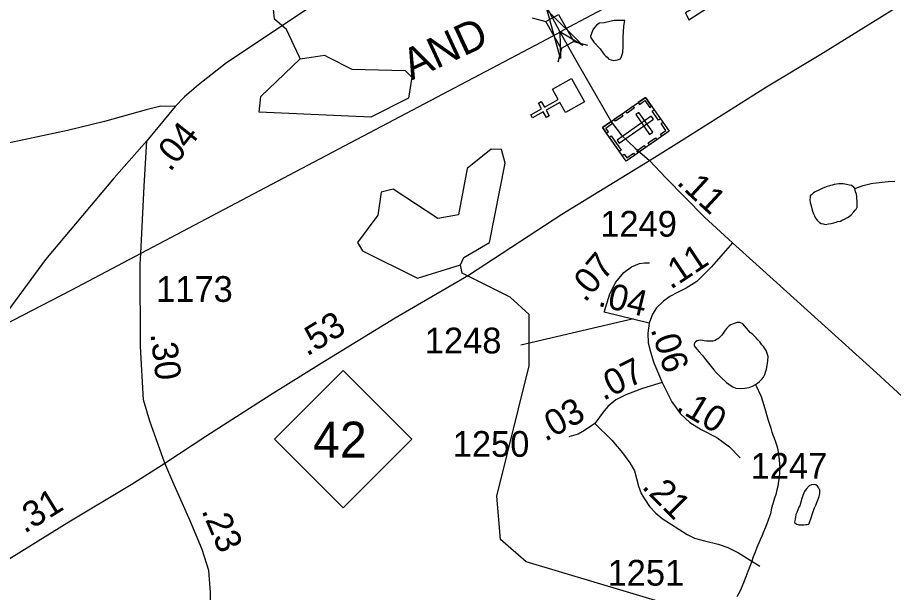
# Model space of a CAD drawing. Extents: x 2001466 to 2224147, y 644118 to 847247.
# Drawn here: x 2043849 to 2048097, y 660715 to 663505 of the extents above; entities that cross this region are included whole.
import ezdxf

# ---------------------------------------------------------------- set-up
doc = ezdxf.new("R2010")
doc.units = 0
for name, color, linetype in [('Exist Cultural Cemetery CELL', 7, 'Continuous'), ('Exist Cultural Church CELL', 7, 'Continuous'), ('Exist Hydrographic Creek Single Shore', 7, 'Continuous'), ('Exist Hydrographic Misc Water Feature', 7, 'Continuous'), ('Exist Railroad Mainline', 7, 'Continuous'), ('Exist Railroad Mainline Label', 7, 'Continuous'), ('Exist Road Primary NC Attributed', 7, 'Continuous'), ('Exist Road Primary NC Service Mileage Hundredths English Label', 7, 'Continuous'), ('Exist Road Primary NC Shield CELL', 7, 'Continuous'), ('Exist Road Primary NC Shield Number Label', 7, 'Continuous'), ('Exist Road Secondary Mileage Hundredths English Label', 7, 'Continuous'), ('Exist Road Secondary Structure Standard Bridge Attributed CELL', 7, 'Continuous'), ('Exist Road Secondary Structure Standard Bridge CELL', 7, 'Continuous'), ('Exist Road Secondary Type 51 Attributed', 7, 'Continuous'), ('Exist Road Secondary Type 51 Number Label', 7, 'Continuous')]:
    doc.layers.add(name, color=color, linetype=linetype)

msp = doc.modelspace()

# ---------------------------------------------------------------- linework, layer by layer
at = {"layer": 'Exist Cultural Cemetery CELL'}
for points in [[(2046894.6, 663117.1), (2047009, 662954.1), (2046800.6, 662807.9), (2046686.2, 662970.8)], [(2046859.2, 663092.2), (2046865.7, 663082.9), (2046892, 663101.4), (2046915.3, 663068.2), (2046924.4, 663074.6), (2046894.6, 663117.1)], [(2046798.4, 663049.6), (2046833.9, 663074.5), (2046840.4, 663065.2), (2046805, 663040.3)], [(2046743.4, 663011), (2046778.9, 663035.9), (2046785.4, 663026.6), (2046750, 663001.7)], [(2046933.3, 663011), (2046922.5, 663026.3), (2046756.5, 662909.8), (2046767.3, 662894.5)], [(2046862.3, 663044.6), (2046847.1, 663033.9), (2046914.7, 662937.5), (2046930, 662948.2)], [(2046937.1, 663056.5), (2046966.9, 663014), (2046957.6, 663007.5), (2046927.8, 663049.9)], [(2046705.2, 662943.8), (2046714.6, 662950.4), (2046702, 662968.4), (2046735.1, 662991.6), (2046728.7, 663000.7), (2046686.2, 662970.9)], [(2046973.5, 662929.2), (2046967, 662938.5), (2046993.4, 662957), (2046970, 662990.2), (2046979.2, 662996.5), (2047009, 662954.1)], [(2046728.6, 662930.4), (2046777.3, 662860.9), (2046768, 662854.4), (2046719.3, 662923.8)], [(2046907.2, 662896.5), (2046942.6, 662921.4), (2046949.2, 662912.1), (2046913.7, 662887.2)], [(2046853.2, 662858.7), (2046888.6, 662883.6), (2046895.2, 662874.2), (2046859.7, 662849.4)], [(2046781.5, 662835), (2046790.9, 662841.6), (2046803.6, 662823.6), (2046836.6, 662846.8), (2046843, 662837.7), (2046800.6, 662807.9)]]:
    msp.add_lwpolyline(points, close=True, dxfattribs=at)
at = {"layer": 'Exist Cultural Church CELL'}
msp.add_lwpolyline([(2046506.8, 663043.4), (2046478.8, 663093), (2046412.4, 663055.7), (2046428.1, 663027.8), (2046414.2, 663020), (2046398.5, 663047.9), (2046346.1, 663018.4), (2046338.2, 663032.4), (2046390.7, 663061.8), (2046375, 663089.7), (2046388.9, 663097.6), (2046404.6, 663069.7), (2046471, 663106.9), (2046442.9, 663157.3), (2046535.7, 663209.4), (2046599.6, 663095.5)], close=True, dxfattribs=at)
at = {"layer": 'Exist Hydrographic Creek Single Shore'}
msp.add_lwpolyline([(2047208.2, 660449.1), (2047192.2, 660541.3), (2046975.3, 660667.1), (2046316.2, 660864.2), (2046191.2, 660971.7), (2046174.1, 661182.1), (2046331.2, 661815.3), (2046331.2, 662064.7), (2046239.1, 662148.6), (2046005.2, 662264.9), (2045997.2, 662304.5)], dxfattribs=at)
at = {"layer": 'Exist Hydrographic Misc Water Feature'}
for q in [(2045216.5, 663312.6), (2045274.7, 663312.6)]:
    msp.add_line((2045220.2, 663304.5), q, dxfattribs=at)
for points in [[(2045216.5, 663312.6), (2045153.2, 663446.9), (2045095.4, 663497.3), (2045086.3, 663596), (2044903.2, 663780.1), (2044503.4, 663719.3)], [(2047088.3, 663527.6), (2047104.5, 663493.6), (2047218.1, 663565.8), (2047198.2, 663593.8), (2047088.3, 663527.6)], [(2046684.7, 663338.9), (2046694.8, 663324.9), (2046702.8, 663316.9), (2046708.7, 663312.8), (2046716.7, 663302.9), (2046728.8, 663298.9), (2046738.9, 663296.9), (2046758.7, 663299), (2046772.7, 663305), (2046778.8, 663315), (2046784.6, 663335), (2046786.6, 663365.1), (2046786.4, 663409), (2046790.3, 663463), (2046794.4, 663491), (2046742.3, 663490.9), (2046694.4, 663478.8), (2046672.4, 663476.8), (2046658.5, 663468.7), (2046646.6, 663456.7), (2046638.6, 663444.7), (2046630.6, 663422.7), (2046628.5, 663414.7), (2046628.7, 663408.7), (2046630.6, 663404.7), (2046644.7, 663384.8), (2046674.7, 663352.8), (2046684.7, 663338.9)], [(2045274.7, 663312.6), (2045337.3, 663321.8), (2045355.3, 663312.6)], [(2045355.3, 663312.6), (2045470.2, 663253.5), (2045729.2, 663248.2), (2045762.2, 663214.8), (2045745.2, 663113.4), (2045562.3, 663022), (2045021.3, 663046.1), (2045029.3, 663121.4), (2045220.2, 663304.5)], [(2045997.2, 662304.5), (2046013.2, 662340.2), (2046138.3, 662413.2), (2046213.3, 662798.8), (2046196.3, 662864.7), (2046146.3, 662865.7), (2046029.2, 662773), (2045988.2, 662547.4), (2045888.3, 662529.8), (2045671.4, 662671.9), (2045613.3, 662656.8), (2045596.3, 662545.5), (2045497.3, 662413), (2045522.3, 662373.1), (2045789.3, 662239.8), (2045997.2, 662304.5)], [(2047909.7, 662675.3), (2047905.6, 662681.3), (2047899.7, 662685.2), (2047893.7, 662689.2), (2047883.7, 662691.2), (2047869.7, 662695.2), (2047853.5, 662697.1), (2047841.6, 662697.1), (2047831.6, 662697.1), (2047809.6, 662695.1), (2047799.6, 662691.1), (2047791.6, 662689), (2047771.7, 662683), (2047751.8, 662675), (2047735.8, 662667), (2047717.8, 662658.9), (2047709.8, 662654.9), (2047699.7, 662644.9), (2047693.8, 662638.9), (2047693.8, 662632.9), (2047691.9, 662620.9), (2047693.8, 662606.9), (2047697.9, 662590.9), (2047703.8, 662570.9), (2047710, 662552.9), (2047714.1, 662542.9), (2047720, 662531), (2047728, 662520.9), (2047738.1, 662510.9), (2047746.1, 662504.9), (2047755.9, 662503), (2047768, 662501), (2047782, 662503.1), (2047795.9, 662505.1), (2047808, 662509.1), (2047819.9, 662511.1), (2047826, 662515.1), (2047840, 662517.1), (2047848, 662521.1), (2047860.1, 662527.2), (2047874, 662535.2), (2047882, 662539.2), (2047891.9, 662547.3), (2047905.8, 662561.3), (2047912, 662569.3), (2047915.9, 662575.3), (2047920, 662581.3), (2047921.8, 662585.3), (2047921.8, 662593.3), (2047921.8, 662601.3), (2047921.8, 662615.2), (2047919.7, 662627.2), (2047919.7, 662637.2), (2047917.7, 662647.3), (2047913.8, 662659.3), (2047911.8, 662667.3), (2047909.7, 662675.3)], [(2047909.7, 662675.3), (2047949.7, 662689.3), (2047989.7, 662699.4), (2048013.7, 662703.5), (2048071.7, 662709.6), (2048103.7, 662711.6)], [(2047427.4, 661724.5), (2047437.5, 661730.5), (2047447.5, 661738.5), (2047459.4, 661750.5), (2047467.4, 661760.6), (2047473.6, 661772.6), (2047477.2, 661784.6), (2047481.3, 661798.6), (2047485.2, 661816.6), (2047487.3, 661838.6), (2047489.1, 661860.6), (2047479.3, 661888.5), (2047473.1, 661898.6), (2047467.2, 661908.6), (2047459, 661916.6), (2047449.2, 661930.5), (2047439.1, 661940.5), (2047431.1, 661950.5), (2047415.1, 661966.5), (2047403, 661976.5), (2047385, 661998.4), (2047366.9, 662018.4), (2047353, 662024.3), (2047339, 662024.3), (2047324.9, 662020.2), (2047308.9, 662014.2), (2047300.9, 662008.2), (2047289, 661998.2), (2047281, 661988.2), (2047275.1, 661978.2), (2047265, 661964.2), (2047257, 661956.2), (2047249, 661948.1), (2047239.2, 661942.1), (2047233, 661938.1), (2047221.1, 661934.1), (2047211.3, 661934.1), (2047201.2, 661934.1), (2047191.2, 661934.1), (2047179.3, 661936), (2047173.2, 661938), (2047163.3, 661940), (2047153.3, 661938), (2047145.3, 661935.9), (2047137.3, 661931.9), (2047133.2, 661927.9), (2047131.3, 661919.9), (2047131.3, 661911.9), (2047137.3, 661903.9), (2047143.2, 661895.9), (2047155.3, 661882), (2047169.3, 661866), (2047187.3, 661844), (2047225.4, 661796.1), (2047239.4, 661780.2), (2047261.5, 661758.2), (2047287.4, 661734.2), (2047309.5, 661718.3), (2047317.5, 661712.3), (2047333.5, 661706.4), (2047355.6, 661704.4), (2047375.5, 661706.5), (2047397.7, 661710.5), (2047413.5, 661716.5), (2047427.4, 661724.5)], [(2047427.4, 661724.5), (2047455.5, 661666.6), (2047473.8, 661608.6), (2047487.9, 661556.7), (2047501.9, 661512.7), (2047508, 661492.7)], [(2047508, 661492.7), (2047524, 661450.8), (2047532, 661426.8), (2047536.1, 661408.8), (2047538.1, 661396.8), (2047540, 661380.8), (2047542.2, 661360.8), (2047544.3, 661336.8), (2047546.1, 661316.8), (2047544.3, 661300.8), (2047542.2, 661270.8), (2047540.4, 661254.8), (2047536.3, 661230.8), (2047532.4, 661212.8), (2047526.5, 661190.8), (2047520.5, 661172.8), (2047512.5, 661144.8), (2047506.6, 661124.8), (2047500.6, 661096.7), (2047490.8, 661070.7), (2047482.8, 661048.8), (2047476.8, 661032.8), (2047466.8, 661008.8), (2047458.8, 660988.7), (2047450.8, 660970.7), (2047435, 660932.7), (2047427, 660910.7), (2047417.2, 660888.6), (2047409, 660862.6), (2047401, 660840.6), (2047391.1, 660816.6), (2047381.3, 660790.6), (2047373.3, 660770.5), (2047359.3, 660734.6), (2047353.4, 660722.6), (2047337.4, 660694.6)], [(2047642.5, 661135), (2047638.6, 661129), (2047628.6, 661103), (2047624.5, 661093), (2047622.6, 661081), (2047620.8, 661073), (2047618.7, 661063), (2047616.7, 661057), (2047618.7, 661053), (2047628.8, 661047), (2047638.6, 661043.1), (2047662.6, 661043.1), (2047672.7, 661045.1), (2047678.6, 661045.1), (2047686.6, 661047.1), (2047690.7, 661055.2), (2047698.7, 661077.2), (2047706.5, 661103.1), (2047714.5, 661125.2), (2047720.6, 661139.2), (2047736.4, 661181.2), (2047740.5, 661195.2), (2047740.3, 661211.2), (2047734.4, 661225.2), (2047728.2, 661231.2), (2047720.2, 661237.1), (2047712.2, 661239.1), (2047700.3, 661237.1), (2047688.2, 661233.1), (2047674.5, 661217), (2047666.5, 661205.1), (2047658.5, 661185.1), (2047652.4, 661171.1), (2047642.5, 661135)]]:
    msp.add_lwpolyline(points, dxfattribs=at)
at = {"layer": 'Exist Railroad Mainline'}
for points in [[(2046464.5, 663426.2), (2046524.6, 663459.1), (2048551.7, 664535.4), (2049194.6, 664876.7), (2049524.4, 665051.8), (2049557.2, 665070.3), (2052622.8, 666680.7), (2055671.2, 668278.9), (2056997.6, 668963.3), (2058840.6, 669936.5)], [(2044448.5, 662360.9), (2045168.8, 662742.2), (2046388.6, 663384.6), (2046464.5, 663426.2)], [(2043613.8, 661924.4), (2043685.3, 661963.1), (2044109.1, 662181.3), (2044448.5, 662360.9)]]:
    msp.add_lwpolyline(points, dxfattribs=at)
at = {"layer": 'Exist Road Primary NC Attributed'}
for points in [[(2046913.8, 662811.7), (2047082.4, 662915.4), (2047481.7, 663167.8), (2047744.4, 663327), (2048387.5, 663726), (2048678.4, 663914.5), (2049061.4, 664156.9), (2049317.6, 664315.1), (2049692.4, 664549.5), (2049926.7, 664696), (2050073.1, 664788.3), (2050246.6, 664892.3), (2050426, 664989)], [(2044562.7, 661341.9), (2044762.5, 661472.9), (2045077, 661676), (2045321.9, 661827.9), (2045680.4, 662047.8), (2046035.7, 662254.1), (2046488.8, 662550.5), (2046747.8, 662708.6), (2046913.8, 662811.7)], [(2043161.8, 660484.8), (2043403.6, 660637.1), (2043704.5, 660815.2), (2044097.5, 661058.1), (2044399.9, 661239.3), (2044562.7, 661341.9)]]:
    msp.add_lwpolyline(points, dxfattribs=at)
at = {"layer": 'Exist Road Primary NC Shield CELL'}
msp.add_lwpolyline([(2045095.3, 661458.7), (2045428.3, 661791.7), (2045761.3, 661458.7), (2045428.3, 661125.7)], close=True, dxfattribs=at)
at = {"layer": 'Exist Road Secondary Structure Standard Bridge Attributed CELL'}
msp.add_lwpolyline([(2046482.2, 663305.8), (2046417.6, 663540.9), (2046591.1, 663369.5), (2046479.2, 663435.7)], close=True, dxfattribs=at)
at = {"layer": 'Exist Road Secondary Structure Standard Bridge CELL'}
for p, q in [((2046344.9, 663503.2), (2046411.4, 663485)), ((2046547.3, 663388.5), (2046613.8, 663370.3)), ((2046487.3, 663354.3), (2046469.1, 663287.8))]:
    msp.add_line(p, q, dxfattribs=at)
msp.add_lwpolyline([(2046472.7, 663519.9), (2046547.6, 663388.7), (2046486.2, 663353.7), (2046411.4, 663485)], close=True, dxfattribs=at)
at = {"layer": 'Exist Road Secondary Type 51 Attributed'}
msp.add_line((2046913, 662022.5), (2046694, 662074.9), dxfattribs=at)
for points in [[(2046205.8, 664180.3), (2046050.1, 664073.4), (2045655.3, 663822), (2045273.2, 663557.9), (2044862.6, 663285.4), (2044725.9, 663177.6), (2044659.4, 663119.5), (2044612.9, 663073)], [(2046233.7, 664047.4), (2046260.1, 663943.2), (2046346.6, 663692.4), (2046414, 663557.4), (2046479.2, 663435.7)], [(2044612.9, 663073), (2044543.8, 663074.1), (2044473.1, 663056.1), (2044271.5, 663000.2), (2044091, 662956.9), (2043589.5, 662850.2), (2043247.5, 662793.1), (2042932.4, 662735), (2042667.5, 662725.5), (2042397.2, 662731.9), (2042042.6, 662767.8), (2041866.8, 662796.3), (2041767.6, 662825.9), (2041627.2, 662858.6), (2041491.5, 662875.5), (2041144.3, 662882.9), (2040923.6, 662890.3), (2040808.6, 662928.3), (2040588.5, 663066.7), (2040278.1, 663276.9), (2040028.5, 663461.8), (2039952.5, 663496.6), (2039878.6, 663524.1)], [(2046479.2, 663435.7), (2046563.5, 663286.8), (2046730.6, 662996.5), (2046776.1, 662934.9), (2046845, 662870.4), (2046913.8, 662811.7)], [(2044612.9, 663073), (2044476.2, 662907.2)], [(2044476.2, 662907.2), (2044316.9, 662726.6), (2043984.3, 662331.5), (2043728.7, 661985.4)], [(2044446.6, 662360), (2044463.1, 662686.4), (2044476.2, 662907.2)], [(2046913.8, 662811.7), (2046993, 662726.6), (2047181.5, 662535.5), (2047317.1, 662412)], [(2047317.1, 662412), (2047214.3, 662295.6), (2047143.2, 662224.5), (2047092.7, 662190.9), (2047049.6, 662170.3), (2047012.2, 662151.6), (2046982.2, 662129.1), (2046948.5, 662095.5), (2046928, 662065.6), (2046913, 662022.5)], [(2047317.1, 662412), (2047529.3, 662218.6), (2048014.4, 661781.3), (2048220.7, 661592.2), (2048349.5, 661460.1), (2048474, 661313.3), (2048683.6, 661045), (2048847.2, 660838), (2049259.4, 660337.3), (2049468.9, 660074.3), (2049591.3, 659904.2), (2049771.3, 659592.6), (2049867.4, 659461.6), (2049949.2, 659385.6), (2050028.3, 659328.5), (2050076.9, 659300)], [(2044562.7, 661341.9), (2044490.5, 661545.6), (2044459.9, 661649.1), (2044445.1, 661909), (2044444.1, 662308.3), (2044446.6, 662360)], [(2046694, 662074.9), (2046722.1, 662164.7), (2046750.2, 662220.8), (2046789.5, 662267.6), (2046826.9, 662295.6), (2046866.2, 662310.6), (2046890.5, 662314.3), (2046914.9, 662314.3)], [(2046913, 662022.5), (2046905.5, 661973.9), (2046907.4, 661927.1), (2046918.6, 661882.3), (2046935.4, 661829.9), (2046974.8, 661734.5)], [(2046974.8, 661734.5), (2046880.9, 661704.7), (2046799.3, 661674.1), (2046751.6, 661650.3), (2046714.2, 661619.7), (2046693.7, 661595.8), (2046649.5, 661534.6)], [(2046974.8, 661734.5), (2047023, 661639.9), (2047065.2, 661582.2), (2047109.6, 661540), (2047165.1, 661506.7), (2047240.6, 661466.8), (2047302.8, 661422.4), (2047353.9, 661369.1)], [(2046649.5, 661534.6), (2046598.4, 661500.6), (2046567.8, 661483.6), (2046523.6, 661470)], [(2046649.5, 661534.6), (2046732, 661453.5), (2046783.1, 661393.5), (2046818.6, 661344.7), (2046840.9, 661304.8), (2046860.8, 661231.5), (2046874.2, 661196), (2046889.7, 661169.4), (2046914.1, 661131.6), (2046945.2, 661100.6), (2046976.3, 661073.9), (2047096.3, 660996.3), (2047131.8, 660978.5), (2047180.7, 660965.2), (2047247.3, 660949.6), (2047293.9, 660934.1), (2047345, 660907.5), (2047449.4, 660843.1)], [(2044775.1, 660145.1), (2044785.7, 660253.9), (2044789.4, 660461.9), (2044784.6, 660715.5), (2044777.2, 660821.1), (2044744.5, 660923.5), (2044685.9, 661063), (2044602.6, 661252.1), (2044562.7, 661341.9)]]:
    msp.add_lwpolyline(points, dxfattribs=at)
at = {"layer": 'Exist Road Secondary Type 51 Number Label'}
msp.add_line((2046836.1, 662043), (2046289.4, 661914.9), dxfattribs=at)

# ---------------------------------------------------------------- texts
at = {"layer": 'Exist Railroad Mainline Label'}
msp.add_text('AND', height=150, rotation=24.7881, dxfattribs=at).set_placement((2045759.1, 663198.3))
at = {"layer": 'Exist Road Primary NC Service Mileage Hundredths English Label'}
for s, rotation, p in [('.53', 31.5317, (2045252.8, 661858.8)), ('.31', 31.7272, (2043882.9, 660999))]:
    msp.add_text(s, height=125, rotation=rotation, dxfattribs=at).set_placement(p)
at = {"layer": 'Exist Road Primary NC Shield Number Label'}
msp.add_text('42', height=175, dxfattribs=at).set_placement((2045282.4, 661369))
at = {"layer": 'Exist Road Secondary Mileage Hundredths English Label'}
for s, rotation, p in [('.04', 51.2352, (2044588.9, 662752.2)), ('.11', 317.3171, (2047041.5, 662699.7)), ('.11', 33.6733, (2047016.9, 662182.2)), ('.07', 49.9518, (2046601.7, 662118.4)), ('.04', 346.5494, (2046659.8, 662107)), ('.30', 276.7407, (2044493.3, 661970.3)), ('.06', 287.8293, (2046918.4, 661992.3)), ('.07', 26.5505, (2046689.9, 661644.2)), ('.10', 329.0527, (2047037.7, 661603.1)), ('.03', 29.0396, (2046408.4, 661445.2)), ('.21', 315.0181, (2046872.3, 661224.5)), ('.23', 293.0617, (2044739.8, 661112.2))]:
    msp.add_text(s, height=125, rotation=rotation, dxfattribs=at).set_placement(p)
at = {"layer": 'Exist Road Secondary Type 51 Number Label'}
for s, p in [('1249', (2046675.2, 662441.5)), ('1173', (2044521, 662125)), ('1248', (2045824.2, 661875.1)), ('1250', (2045959.6, 661373.4)), ('1247', (2047404.3, 661267)), ('1251', (2046710.6, 660748.4))]:
    msp.add_text(s, height=125, dxfattribs=at).set_placement(p)

doc.saveas('drawing.dxf')
